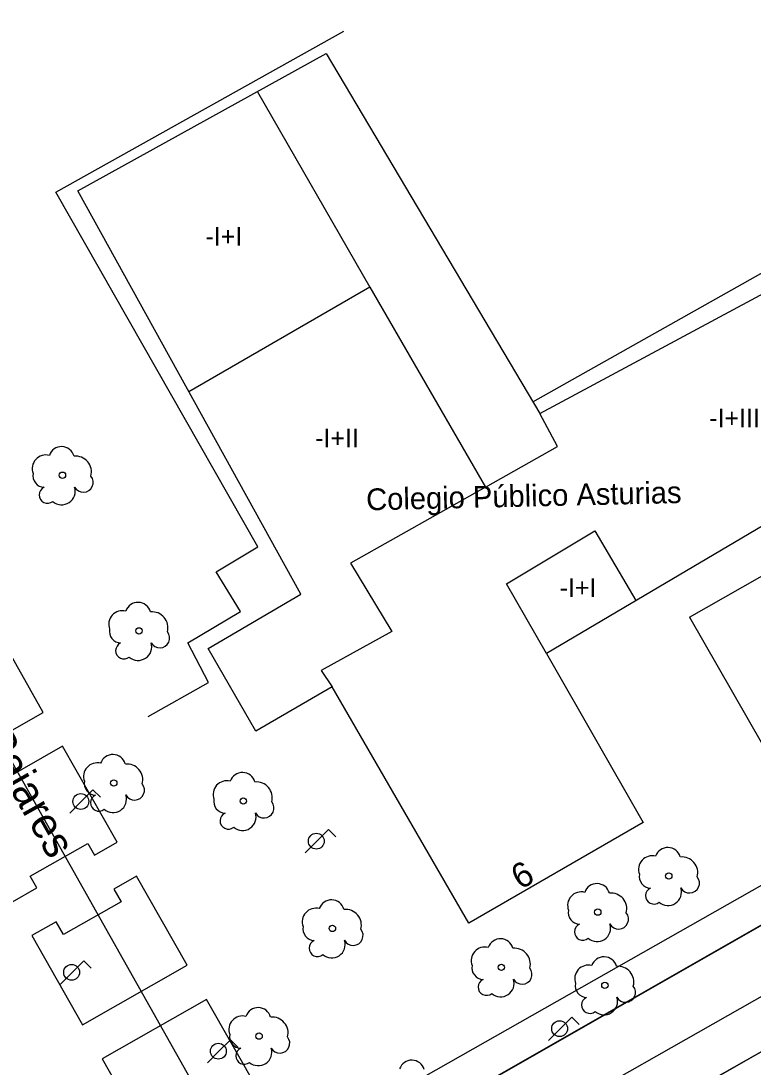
# Model space of a CAD drawing. Extents: x 282771 to 285132, y 4823109 to 4825496.
# Drawn here: x 283939.7 to 283998.6, y 4823604.2 to 4823688.4 of the extents above; entities that cross this region are included whole.
import ezdxf

# ---------------------------------------------------------------- set-up
doc = ezdxf.new("R2010")
doc.units = 0
for name, color, linetype in [('ACERA-BORDILLO', 7, 'Continuous'), ('ACERA-INTERIOR', 7, 'Continuous'), ('ARBOL', 7, 'Continuous'), ('CALLE-EJE', 7, 'Continuous'), ('CALLE-TEXTO', 7, 'Continuous'), ('COLEGIO-AREA', 7, 'Continuous'), ('COLEGIO-TEXTO', 7, 'Continuous'), ('EDIFICIO', 7, 'Continuous'), ('FAROLA', 7, 'Continuous'), ('MEDIANERA', 7, 'Continuous'), ('NUM-PORTAL', 7, 'Continuous'), ('TXT-ALTURA-EDIFICIO', 7, 'Continuous'), ('ZONA-VERDE', 7, 'Continuous')]:
    doc.layers.add(name, color=color, linetype=linetype)

msp = doc.modelspace()

# ---------------------------------------------------------------- linework, layer by layer
at = {"layer": 'ACERA-BORDILLO'}
for points in [[(284024.929, 4823620.049), (283992.33, 4823601.449), (283949.26, 4823577.069), (283935.12, 4823568.939), (283933.4, 4823567.949), (283932.33, 4823566.949), (283931.39, 4823566.199), (283930.57, 4823565.249), (283929.82, 4823564.239), (283928.99, 4823562.979), (283928.29, 4823561.449), (283927.62, 4823559.349), (283927.3, 4823557.699), (283927.3, 4823555.899), (283927.35, 4823553.859)], [(283844.251, 4823534.009), (283878.211, 4823553.289), (283884.587, 4823557.06), (283887.226, 4823552.047), (283893.251, 4823555.509), (283920.41, 4823571.129), (283933.38, 4823578.639), (283952.39, 4823589.289), (283971.49, 4823599.689), (284001.789, 4823617.029)]]:
    msp.add_lwpolyline(points, dxfattribs=at)
at = {"layer": 'ACERA-INTERIOR'}
for p, q in [((283980.899, 4823657.735), (284047.145, 4823695.022)), ((283993.505, 4823640.391), (284010.593, 4823650.147)), ((283993.505, 4823640.391), (284002.83, 4823624.062))]:
    msp.add_line(p, q, dxfattribs=at)
msp.add_lwpolyline([(283949.957, 4823632.39), (283954.811, 4823635.13), (283953.152, 4823638.326), (283957.383, 4823640.858), (283955.433, 4823644.054), (283958.794, 4823646.047), (283942.542, 4823674.596), (283965.71, 4823687.548)], dxfattribs=at)
at = {"layer": 'ARBOL'}
for centre in [(283943.07, 4823651.818), (283949.22, 4823639.288), (283947.196, 4823627.04), (283957.613, 4823625.594), (283991.83, 4823619.559), (283986.123, 4823616.652), (283964.78, 4823615.339), (283978.367, 4823612.212), (283986.69, 4823610.759), (283958.883, 4823606.669)]:
    msp.add_circle(centre, 0.255, dxfattribs=at)
for centre, radius, start, end in [((283941.74, 4823652.348), 1.097, 75.4318, 200.55608), ((283943, 4823653.078), 1.038, 15.64228, 161.38435), ((283944.13, 4823652.078), 1.272, 345.03273, 95.79925), ((283941.63, 4823651.778), 0.935, 168.59898, 268.13236), ((283944.74, 4823651.248), 0.797, 208.96246, 38.99103), ((283941.87, 4823650.228), 0.672, 113.73672, 309.4725), ((283943.01, 4823650.528), 1.086, 228.95447, 17.92796), ((283949.15, 4823640.548), 1.038, 15.64228, 161.38435), ((283947.89, 4823639.818), 1.097, 75.4318, 200.55608), ((283950.28, 4823639.548), 1.272, 345.03273, 95.79925), ((283947.78, 4823639.248), 0.935, 168.59898, 268.13236), ((283950.89, 4823638.718), 0.797, 208.96246, 38.99103), ((283948.02, 4823637.698), 0.672, 113.73672, 309.4725), ((283949.16, 4823637.998), 1.086, 228.95447, 17.92796), ((283947.126, 4823628.3), 1.038, 15.64228, 161.38435), ((283945.866, 4823627.57), 1.097, 75.4318, 200.55608), ((283948.256, 4823627.3), 1.272, 345.03273, 95.79925), ((283945.756, 4823627), 0.935, 168.59898, 268.13236), ((283956.283, 4823626.124), 1.097, 75.4318, 200.55608), ((283957.543, 4823626.854), 1.038, 15.64228, 161.38435), ((283948.866, 4823626.47), 0.797, 208.96246, 38.99103), ((283958.673, 4823625.854), 1.272, 345.03273, 95.79925), ((283945.996, 4823625.45), 0.672, 113.73672, 309.4725), ((283947.136, 4823625.75), 1.086, 228.95447, 17.92796), ((283956.173, 4823625.554), 0.935, 168.59898, 268.13236), ((283959.283, 4823625.024), 0.797, 208.96246, 38.99103), ((283956.413, 4823624.004), 0.672, 113.73672, 309.4725), ((283957.553, 4823624.304), 1.086, 228.95447, 17.92796), ((283991.76, 4823620.819), 1.038, 15.64228, 161.38435), ((283990.5, 4823620.089), 1.097, 75.4318, 200.55608), ((283992.89, 4823619.819), 1.272, 345.03273, 95.79925), ((283990.39, 4823619.519), 0.935, 168.59898, 268.13236), ((283986.053, 4823617.912), 1.038, 15.64225, 161.38431), ((283993.5, 4823618.989), 0.797, 208.96246, 38.99103), ((283984.793, 4823617.182), 1.097, 75.43176, 200.55605), ((283987.183, 4823616.912), 1.272, 345.0327, 95.79922), ((283990.63, 4823617.969), 0.672, 113.73672, 309.4725), ((283991.77, 4823618.269), 1.086, 228.95447, 17.92796), ((283964.71, 4823616.599), 1.038, 15.64228, 161.38435), ((283963.45, 4823615.869), 1.097, 75.4318, 200.55608), ((283965.84, 4823615.599), 1.272, 345.03273, 95.79925), ((283984.683, 4823616.612), 0.935, 168.59894, 268.13232), ((283987.793, 4823616.082), 0.797, 208.96243, 38.99099), ((283963.34, 4823615.299), 0.935, 168.59898, 268.13236), ((283984.923, 4823615.062), 0.672, 113.73669, 309.47246), ((283986.063, 4823615.362), 1.086, 228.95444, 17.92792), ((283966.45, 4823614.769), 0.797, 208.96246, 38.99103), ((283963.58, 4823613.749), 0.672, 113.73672, 309.4725), ((283964.72, 4823614.049), 1.086, 228.95447, 17.92796), ((283977.037, 4823612.742), 1.097, 75.43176, 200.55605), ((283978.297, 4823613.472), 1.038, 15.64225, 161.38431), ((283979.427, 4823612.472), 1.272, 345.0327, 95.79922), ((283986.62, 4823612.019), 1.038, 15.64228, 161.38435), ((283976.927, 4823612.172), 0.935, 168.59894, 268.13232), ((283980.037, 4823611.642), 0.797, 208.96243, 38.99099), ((283985.36, 4823611.289), 1.097, 75.4318, 200.55608), ((283987.75, 4823611.019), 1.272, 345.03273, 95.79925), ((283977.167, 4823610.622), 0.672, 113.73669, 309.47246), ((283978.307, 4823610.922), 1.086, 228.95444, 17.92792), ((283985.25, 4823610.719), 0.935, 168.59898, 268.13236), ((283988.36, 4823610.189), 0.797, 208.96246, 38.99103), ((283985.49, 4823609.169), 0.672, 113.73672, 309.4725), ((283986.63, 4823609.469), 1.086, 228.95447, 17.92796), ((283958.813, 4823607.929), 1.038, 15.64228, 161.38435), ((283957.553, 4823607.199), 1.097, 75.4318, 200.55608), ((283959.943, 4823606.929), 1.272, 345.03273, 95.79925), ((283957.443, 4823606.629), 0.935, 168.59898, 268.13236), ((283960.553, 4823606.099), 0.797, 208.96246, 38.99103), ((283957.683, 4823605.079), 0.672, 113.73672, 309.4725), ((283958.823, 4823605.379), 1.086, 228.95447, 17.92796), ((283971.16, 4823603.699), 1.038, 15.64228, 161.38435)]:
    msp.add_arc(centre, radius, start, end, dxfattribs=at)
at = {"layer": 'CALLE-EJE'}
for points in [[(283961.69, 4823588.479), (283904.71, 4823689.628)], [(284130.168, 4823684.268), (283961.69, 4823588.479)]]:
    msp.add_lwpolyline(points, dxfattribs=at)
at = {"layer": 'COLEGIO-AREA'}
msp.add_lwpolyline([(283962.23, 4823642.238), (283944.3, 4823674.708), (283964.29, 4823685.748), (283981.46, 4823656.788), (284001.379, 4823667.488), (284008.969, 4823653.398), (283981.99, 4823637.478), (283989.76, 4823623.868), (283975.76, 4823615.759), (283964.77, 4823634.778), (283958.62, 4823631.228), (283954.78, 4823637.868)], close=True, dxfattribs=at)
at = {"layer": 'EDIFICIO'}
msp.add_lwpolyline([(283962.23, 4823642.238), (283944.3, 4823674.708), (283964.29, 4823685.748), (283981.46, 4823656.788), (284001.379, 4823667.488), (284008.969, 4823653.398), (283981.99, 4823637.478), (283989.76, 4823623.868), (283975.76, 4823615.759), (283964.77, 4823634.778), (283958.62, 4823631.228), (283954.78, 4823637.868), (283962.23, 4823642.238)], dxfattribs=at)
at = {"layer": 'FAROLA'}
for p, q in [((283945.526, 4823626.489), (283944.586, 4823625.559)), ((283946.116, 4823625.899), (283945.526, 4823626.489)), ((283944.586, 4823625.559), (283943.656, 4823624.619)), ((283964.462, 4823623.294), (283963.522, 4823622.364)), ((283965.052, 4823622.704), (283964.462, 4823623.294)), ((283963.522, 4823622.364), (283962.592, 4823621.424)), ((283944.785, 4823612.735), (283943.845, 4823611.805)), ((283945.375, 4823612.145), (283944.785, 4823612.735)), ((283943.845, 4823611.805), (283942.915, 4823610.865)), ((283984.03, 4823608.199), (283983.09, 4823607.269)), ((283984.62, 4823607.609), (283984.03, 4823608.199)), ((283983.09, 4823607.269), (283982.16, 4823606.329)), ((283956.591, 4823606.384), (283955.651, 4823605.454)), ((283957.181, 4823605.794), (283956.591, 4823606.384)), ((283955.651, 4823605.454), (283954.721, 4823604.514))]:
    msp.add_line(p, q, dxfattribs=at)
for centre in [(283944.546, 4823625.559), (283963.482, 4823622.364), (283943.805, 4823611.805), (283983.05, 4823607.269), (283955.611, 4823605.454)]:
    msp.add_circle(centre, 0.637, dxfattribs=at)
at = {"layer": 'MEDIANERA'}
for points in [[(283958.75, 4823682.688), (283967.8, 4823666.958)], [(283967.8, 4823666.958), (283953.23, 4823658.528)], [(283967.8, 4823666.958), (283977.08, 4823650.858)], [(283977.08, 4823650.858), (283982.87, 4823654.138), (283981.46, 4823656.788)], [(283977.08, 4823650.858), (283966.24, 4823644.728), (283969.55, 4823639.228), (283963.88, 4823636.098), (283964.77, 4823634.778)], [(283981.99, 4823637.478), (283978.77, 4823643.078), (283985.89, 4823647.338), (283989.19, 4823641.728)]]:
    msp.add_lwpolyline(points, dxfattribs=at)
at = {"layer": 'ZONA-VERDE'}
for p, q in [((284025.459, 4823630.598), (283969.904, 4823598.826)), ((283968.528, 4823601.354), (284016.559, 4823628.619)), ((283979.439, 4823594.152), (284018.633, 4823616.457))]:
    msp.add_line(p, q, dxfattribs=at)
for points in [[(283941.526, 4823632.731), (283937.084, 4823640.543), (283935.261, 4823639.507), (283935.867, 4823638.441), (283931.235, 4823635.807), (283930.629, 4823636.874), (283928.675, 4823635.763), (283933.116, 4823627.95), (283941.526, 4823632.731)], [(283947.472, 4823622.272), (283943.079, 4823629.999), (283934.67, 4823625.218), (283939.062, 4823617.491), (283941.017, 4823618.602), (283940.486, 4823619.536), (283945.118, 4823622.169), (283945.649, 4823621.236), (283947.472, 4823622.272)], [(283949.024, 4823619.542), (283947.201, 4823618.505), (283947.784, 4823617.48), (283943.152, 4823614.846), (283942.569, 4823615.872), (283940.615, 4823614.761), (283944.692, 4823607.589), (283953.101, 4823612.37), (283949.024, 4823619.542)], [(283958.888, 4823602.192), (283954.667, 4823609.616), (283946.257, 4823604.836), (283950.478, 4823597.411), (283958.888, 4823602.192)]]:
    msp.add_lwpolyline(points, dxfattribs=at)

# ---------------------------------------------------------------- texts
at = {"layer": 'CALLE-TEXTO'}
msp.add_text('Calle Puerto de Pajares', height=2.5, rotation=299.39356, dxfattribs=at).set_placement((283924.715, 4823651.568))
at = {"layer": 'COLEGIO-TEXTO'}
msp.add_text('Colegio Público Asturias', height=1.75, rotation=1.3409, dxfattribs=at).set_placement((283967.514, 4823648.988))
at = {"layer": 'NUM-PORTAL'}
msp.add_text('6', height=2, rotation=29.85004, dxfattribs=at).set_placement((283979.895, 4823618.418))
at = {"layer": 'TXT-ALTURA-EDIFICIO'}
for s, p in [('-I+I', (283954.576, 4823670.298)), ('-I+III', (283995.085, 4823655.678)), ('-I+II', (283963.396, 4823654.068)), ('-I+I', (283983.056, 4823642.028))]:
    msp.add_text(s, height=1.5, rotation=0.00004, dxfattribs=at).set_placement(p)

doc.saveas('drawing.dxf')
